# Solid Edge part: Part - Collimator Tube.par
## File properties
Author: hhakima
Template: Normal.par
Last saved by: hhakima
Revision: 6
Application: Solid Edge
Accuracy: 0.990
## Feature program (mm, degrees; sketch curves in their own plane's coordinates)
sketch for "unnamed Protrusion 1" plane through (0, 0, 0) normal (0, 0, 1) x-axis (1, 0, 0)
  circle centre (0, 0) radius 5.25
extrude "unnamed Protrusion 1" add finite 11 along -normal
sketch for "ExtrudedCutout_1" plane through (0, 0, 0) normal (0, 0, 1) x-axis (1, 0, 0)
  circle centre (0, 0) radius 5
extrude "ExtrudedCutout_1" cut finite 1.5 along -normal
sketch for "unnamed Cutout 1" plane through (0, 0, -1.5) normal (0, 0, 1) x-axis (1, 0, 0)
  circle centre (0, 0) radius 3.3
extrude "unnamed Cutout 1" cut to key point along -normal
sketch for "ExtrudedCutout_3" plane through (0, 0, -11) normal (0, 0, -1) x-axis (-1, 0, 0)
  circle centre (0, 0) radius 4.5
extrude "ExtrudedCutout_3" cut finite 2 along -normal
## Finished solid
Body 1: solid body, 8 faces, 8 edges, 0 vertices.
  Faces by surface: cylinder 4, plane 4
  Edges by curve: circle 8
Bounding box of the edges (mm): 10.500 x 10.500 x 11.000, from (-5.25, -5.25, -11) to (5.25, 5.25, 0).
Cylindrical faces by radius (mm): R3.3 x1, R4.5 x1, R5 x1, R5.25 x1
Planar faces by outward normal: +z 2, -z 2
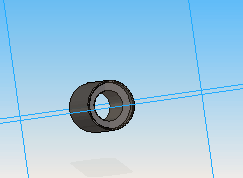
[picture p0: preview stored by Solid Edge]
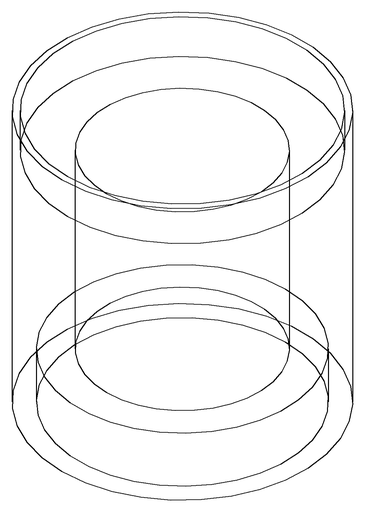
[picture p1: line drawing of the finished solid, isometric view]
